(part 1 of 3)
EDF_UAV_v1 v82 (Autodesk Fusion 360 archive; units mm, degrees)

design "EDF_UAV_v1" references "UAV_test_rig", "fin_mount", "servo_savox_SH-0264MG"
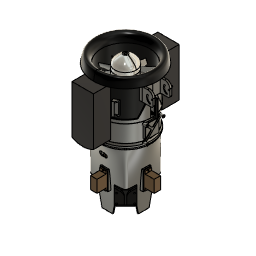
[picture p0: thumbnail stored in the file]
sketch "Sketch1" plane through (0, 0, 0) normal (0, 0, 1) x axis (1, 0, 0)
  circle C1 centre (0, 0) radius 44.7
  circle C2 centre (0, 0) radius 46.75
  point P1 (0, 0)
  point P2 (0, 0)
  coincident P1 P2
  concentric C1 C2
  dimension "d1" diameter C1 = 89.4
  dimension "d486" diameter C2 = 93.5
extrude "Extrude1" new body sketch "Sketch1" profile of C1 along normal blind 63
sketch "Sketch2" plane through (0, 0, 0) normal (0, 0, 1) x axis (1, 0, 0)
  circle C1 centre (0, 0) radius 21.6
  dimension "d51" diameter C1 = 43.2
extrude "Extrude2" new body sketch "Sketch2" along normal blind 40
sketch "Sketch8" plane through (0, 0, 0) normal (0, 0, -1) x axis (1, 0, 0)
  circle C1 centre (0, 0) radius 21.6
  circle C2 centre (0, 0) radius 21.6
  circle C3 centre (0, 0) radius 20
  point P1 (0, 0)
  point P3 (0, 0)
  coincident P1 P3
  concentric C2 C3
  equal C1 C2
  dimension "d176" diameter C3 = 40
extrude "Extrude7" cut sketch "Sketch8" profile of C3 against normal blind 30
sketch "Sketch9" plane through (0, 0, 40) normal (0, 0, 1) x axis (-1, 0, 0)
  line L1 (0, 27) -> (0, -28)
  line L2 (21.3145, -3.5) -> (12.25, -3.5)
  line L3 (21.3145, 3.5) -> (12.25, 3.5)
  line L4 (-14.3541, 0) -> (31.6459, 0)
  line L5 (-21.3145, 3.5) -> (-12.25, 3.5)
  line L6 (-21.3145, -3.5) -> (-12.25, -3.5)
  circle C1 centre (0, 0) radius 21.6
  circle C2 centre (0, 0) radius 21.6
  arc A1 centre (0, 0) radius 21.6 clockwise from (21.3145, 3.5) to (21.3145, -3.5)
  arc A2 centre (0, 0) radius 21.6 clockwise from (0, -21.6) to (0, 21.6)
  arc A3 centre (12.25, 0) radius 3.5 clockwise from (12.25, -3.5) to (12.25, 3.5)
  arc A4 centre (0, 0) radius 21.6 clockwise from (-21.3145, -3.5) to (-21.3145, 3.5)
  arc A5 centre (-12.25, 0) radius 3.5 clockwise from (-12.25, 3.5) to (-12.25, -3.5)
  point P5 (0, 0)
  point P7 (0, 0)
  point P12 (0, -21.6)
  point P13 (0, 21.6)
  point P14 (0, 0)
  point P6 (12.25, 0)
  point P17 (21.3145, 3.5)
  point P18 (21.3145, 3.5)
  point P9 (12.25, -3.5)
  point P25 (-12.25, -3.5)
  point P10 (21.3145, -3.5)
  point P20 (-21.3145, -3.5)
  point P11 (12.25, 3.5)
  point P22 (-12.25, 3.5)
  point P23 (-21.3145, 3.5)
  point P21 (-21.3145, 3.5)
  vertical L1
  coincident L1 P5
  coincident P5 P7
  equal C2 A1
  horizontal L2
  horizontal L3
  tangent L2 A3
  tangent L3 A3
  coincident L1 P12
  coincident L1 P13
  concentric A1 A2
  horizontal L4
  coincident P14 L4
  coincident P6 L4
  coincident A1 P17
  coincident L3 P18
  symmetric L1 P9 P25
  symmetric L1 P10 P20
  symmetric L1 P11 P22
  symmetric L1 A1 A4
  symmetric L1 A3 A5
  symmetric L1 P17 P23
  symmetric L1 P18 P21
  dimension "d177" distance L2 L3 = 7
  dimension "d178" = 24.5
extrude "Extrude8" cut sketch "Sketch9" profile of C1 A3 A2 C2 L2 L3 A4 L5 A5 L6 against normal blind 7
sketch "Sketch10" plane through (0, 0, 40) normal (0, 0, 1) x axis (-1, 0, 0)
  line L1 (-12.25, 3.5) -> (-21.3145, 3.5)
  line L2 (-21.3145, -3.5) -> (-12.25, -3.5)
  line L3 (12.25, -3.5) -> (21.3145, -3.5)
  line L4 (21.3145, 3.5) -> (12.25, 3.5)
  line L5 (-28.5897, 0) -> (22.8656, 0)
  line L6 (0, 21.6) -> (0, -27)
  line L7 (0, 0) -> (7.7782, -7.7782)
  line L8 (-7.7782, -7.7782) -> (0, 0)
  arc A1 centre (-12.25, 0) radius 3.5 clockwise from (-12.25, 3.5) to (-12.25, -3.5)
  arc A2 centre (0, 0) radius 21.6 clockwise from (21.3145, -3.5) to (-21.3145, -3.5)
  arc A3 centre (12.25, 0) radius 3.5 clockwise from (12.25, -3.5) to (12.25, 3.5)
  arc A4 centre (0, 0) radius 21.6 clockwise from (-21.3145, 3.5) to (21.3145, 3.5)
  arc A5 centre (0, 0) radius 11 clockwise from (7.7782, -7.7782) to (-7.7782, -7.7782)
  arc A6 centre (0, 0) radius 12.5 clockwise from (8.8388, -8.8388) to (-8.8388, -8.8388)
  arc A7 centre (0, 0) radius 9.5 clockwise from (6.7175, -6.7175) to (-6.7175, -6.7175)
  arc A8 centre (-7.7782, -7.7782) radius 1.5 clockwise from (-8.8388, -8.8388) to (-6.7175, -6.7175)
  arc A9 centre (7.7782, -7.7782) radius 1.5 clockwise from (6.7175, -6.7175) to (8.8388, -8.8388)
  circle C1 centre (0, 0) radius 7
  arc A10 centre (0, 0) radius 9.5 clockwise from (-6.7175, 6.7175) to (6.7175, 6.7175)
  arc A11 centre (7.7782, 7.7782) radius 1.5 clockwise from (8.8388, 8.8388) to (6.7175, 6.7175)
  arc A12 centre (0, 0) radius 12.5 clockwise from (-8.8388, 8.8388) to (8.8388, 8.8388)
  arc A13 centre (-7.7782, 7.7782) radius 1.5 clockwise from (-6.7175, 6.7175) to (-8.8388, 8.8388)
  circle C2 centre (12.25, 0) radius 1.5
  point P17 (0, 0)
  point P23 (0, 0)
  point P18 (8.8388, 8.8388)
  point P24 (8.8388, -8.8388)
  point P13 (-8.8388, -8.8388)
  point P15 (-8.8388, 8.8388)
  point P19 (-6.7175, 6.7175)
  point P25 (-6.7175, -6.7175)
  point P22 (6.7175, 6.7175)
  point P26 (6.7175, -6.7175)
  point P1 (0, 0)
  point P32 (0, 21.6)
  point P14 (-7.7782, -7.7782)
  point P30 (7.7782, -7.7782)
  point P33 (7.7782, -7.7782)
  point P34 (0, 0)
  point P35 (0, 0)
  point P36 (-7.7782, -7.7782)
  point P29 (12.25, 0)
  tangent A6 A8
  tangent A7 A8
  tangent A7 A9
  tangent A6 A9
  coincident P17 P23
  coincident P17 L5
  symmetric P18 P24 L5
  symmetric P13 P15 L5
  symmetric P19 P25 L5
  symmetric P22 P26 L5
  symmetric A6 L5 A12
  symmetric A8 L5 A13
  symmetric A7 L5 A10
  symmetric A9 L5 A11
  horizontal L5
  coincident P1 L5
  coincident P1 P17
  midpoint A4 P32
  vertical L6
  symmetric P14 P30 L6
  coincident P30 P33
  coincident P17 P34
  coincident P1 P35
  coincident P14 P36
  coincident P29 L5
  concentric A3 C2
  dimension "d179" diameter C1 = 14
  dimension "d180" diameter C2 = 3
  dimension "d181" distance A6 A7 = 3
  dimension "d182" diameter A5 = 22
  dimension "d183" angle L7 L8 = 90
extrude "Extrude9" cut sketch "Sketch10" profile of A6 A7 A8 A9 C1 A10 A11 A12 A13 no distance stored
work_plane "WorkPlane1" RotateAngle 0
sketch "Sketch3" plane through (0, -21.6, 25.8865) normal (0, -1, 0) x axis (1, 0, 0)
  curve K1 (1, 3) -> (3, -23.8865)
  curve K2 (3, -23.8865) -> (1, 3)
  line L1 (-44.7, -25.8865) -> (44.7, -25.8865)
  point P2 (3, -23.8865)
  point P4 (4, 6.1135)
  dimension "d10" distance P2 L1 = 2
  dimension "d11" distance P2 P4 = 30
extrude "Extrude3" add sketch "Sketch3" profile of K1 K2 to an object Side2Offset 0
circular_pattern "C-Pattern1" TotalAngle 360
work_plane "WorkPlane2" RotateAngle 0
sketch "Sketch5" plane through (-44.7, 0, 31.321) normal (1, 0, 0) x axis (0, 1, 0)
  line L1 (3.2, -1.321) -> (0, -1.321)
  line L2 (3.2, -31.321) -> (3.2, -1.321)
  line L3 (0, -31.321) -> (3.2, -31.321)
  line L4 (0, -1.321) -> (0, -31.321)
  point P6 (0, -31.321)
  point P4 (3.2, -31.321)
  point P5 (0, -31.321)
  point P3 (3.2, -1.321)
  horizontal L1
  vertical L2
  horizontal L3
  vertical L4
  coincident L3 P6
  coincident L4 P6
  dimension "d27" distance P4 P5 = 3.2
  dimension "d28" distance P3 P4 = 30
extrude "Extrude5" add sketch "Sketch5" blind -12 Side2Offset 0
sketch "Sketch6" plane through (0, 0, 0) normal (0, -1, 0) x axis (1, 0, 0)
  line L1 (-46.75, 0) -> (-56.7, 0)
  line L2 (-56.7, 0) -> (-56.7, 30)
  line L3 (-56.7, 30) -> (-46.75, 30)
  line L4 (-46.75, 30) -> (-46.75, 0)
  circle C1 centre (-51.2, 22.5) radius 1.65
  circle C2 centre (-51.2, 7.5) radius 1.65
  point P6 (-51.2, 22.5)
  point P7 (-51.2, 7.5)
  vertical P6 P7
  equal C1 C2
  dimension "d39" diameter C1 = 3.3
  dimension "d40" distance L2 P6 = 5.5
  dimension "d42" distance P6 P7 = 15
  dimension "d46" distance L1 P7 = 7.5
extrude "Extrude6" cut sketch "Sketch6" profile of C1 C2 no distance stored
mirror "Mirror2" mirrorStitchTolerance 0.1
sketch "Sketch7" plane through (0, 0, 40) normal (0, 0, 1) x axis (-1, 0, 0)
  line L1 (-12.25, 3.5) -> (-21.3145, 3.5)
  line L2 (-21.3145, -3.5) -> (-12.25, -3.5)
  line L3 (12.25, -3.5) -> (21.3145, -3.5)
  line L4 (21.3145, 3.5) -> (12.25, 3.5)
  circle C1 centre (0, 0) radius 20
  circle C2 centre (0, 0) radius 21.6
  arc A1 centre (-12.25, 0) radius 3.5 clockwise from (-12.25, 3.5) to (-12.25, -3.5)
  arc A2 centre (12.25, 0) radius 3.5 clockwise from (12.25, -3.5) to (12.25, 3.5)
  arc A3 centre (0, 0) radius 21.6 clockwise from (-21.3145, 3.5) to (21.3145, 3.5)
  arc A4 centre (0, 0) radius 21.6 clockwise from (21.3145, -3.5) to (-21.3145, -3.5)
  arc A5 centre (0, 0) radius 9.5 clockwise from (6.7175, -6.7175) to (-6.7175, -6.7175)
  arc A6 centre (7.7782, -7.7782) radius 1.5 clockwise from (6.7175, -6.7175) to (8.8388, -8.8388)
  arc A7 centre (0, 0) radius 12.5 clockwise from (8.8388, -8.8388) to (-8.8388, -8.8388)
  arc A8 centre (-7.7782, -7.7782) radius 1.5 clockwise from (-8.8388, -8.8388) to (-6.7175, -6.7175)
  circle C3 centre (0, 0) radius 7
  arc A9 centre (0, 0) radius 9.5 clockwise from (-6.7175, 6.7175) to (6.7175, 6.7175)
  arc A10 centre (-7.7782, 7.7782) radius 1.5 clockwise from (-6.7175, 6.7175) to (-8.8388, 8.8388)
  arc A11 centre (0, 0) radius 12.5 clockwise from (-8.8388, 8.8388) to (8.8388, 8.8388)
  arc A12 centre (7.7782, 7.7782) radius 1.5 clockwise from (8.8388, 8.8388) to (6.7175, 6.7175)
  arc A13 centre (0, 0) radius 21.6 clockwise from (-21.3145, 3.5) to (21.3145, 3.5)
  concentric C1 C2
  dimension "d134" diameter C1 = 40
extrude "Extrude10" cut sketch "Sketch7" profile of C1 C2 against normal blind 7
chamfer "Chamfer2" distance 7
sketch "Sketch1" plane through (0, 0, 0) normal (0, 0, 1) x axis (1, 0, 0)
  circle C1 centre (0, 0) radius 20
  circle C2 centre (0, 0) radius 21.6
  circle C3 centre (0, 0) radius 21.6
  point P1 (0, 0)
  point P2 (0, 0)
  coincident P1 P2
  concentric C1 C2
  equal C2 C3
  dimension "d124" diameter C1 = 40
extrude "Extrude1" new body sketch "Sketch1" profile of C1 along normal blind 23.5
sketch "Sketch2" plane through (0, 0, 23.5) normal (0, 0, 1) x axis (-1, 0, 0)
  circle C1 centre (0, 0) radius 20
  circle C2 centre (0, 0) radius 18.25
  circle C3 centre (0, 0) radius 20
  point P1 (0, 0)
  point P3 (0, 0)
  coincident P1 P3
  concentric C2 C3
  equal C1 C3
  dimension "d75" diameter C2 = 36.5
extrude "Extrude2" cut sketch "Sketch2" against normal blind 3
sketch "Sketch3" plane through (0, 0, 23.5) normal (0, 0, 1) x axis (-1, 0, 0)
  circle C1 centre (0, 0) radius 18.25
  circle C2 centre (0, 0) radius 4
  point P1 (0, 0)
  point P3 (0, 0)
  coincident P1 P3
  dimension "d78" diameter C2 = 8
extrude "Extrude3" cut sketch "Sketch3" profile of C2 no distance stored
sketch "Sketch4" plane through (0, 0, 0) normal (0, 0, -1) x axis (1, 0, 0)
  circle C1 centre (0, 0) radius 4
  circle C2 centre (0, 0) radius 20
  circle C3 centre (0, 0) radius 6
  point P1 (0, 0)
  point P3 (0, 0)
  coincident P1 P3
  dimension "d80" diameter C3 = 12
extrude "Extrude4" cut sketch "Sketch4" profile of C1 C3 against normal blind 8
sketch "Sketch5" plane through (0, 0, 0) normal (0, 0, -1) x axis (1, 0, 0)
  circle C1 centre (0, 0) radius 6
  circle C2 centre (0, 0) radius 20
  circle C3 centre (0, 0) radius 6
  circle C4 centre (0, 0) radius 12.5
  concentric C1 C3
  equal C1 C3
  concentric C3 C4
  dimension "d84" diameter C4 = 25
extrude "Extrude5" cut sketch "Sketch5" profile of C1 C3 C4 against normal blind 12
chamfer "Chamfer1" distance 7 distance 12
ground "Ground1"
work_plane "WorkPlane1" RotateAngle 0
sketch "Sketch7" plane through (-3.2407, -19.7357, 12.3408) normal (-0.162, -0.9868, 0) x axis (-0.9868, 0.162, 0)
  curve K1 (0, -7) -> (0, -7)
work_plane "WorkPlane2" AlongDistance 22
sketch "Sketch8" plane through (-6.8056, -41.445, 12.3408) normal (-0.162, -0.9868, 0) x axis (-0.9868, 0.162, 0)
  curve K1 (1, -2) -> (1, -2)
loft "Loft1" sketch "Sketch7" + "Sketch8"
extrude "Extrude6" add of existing geometry to an object
circular_pattern "C-Pattern1" countU 11 TotalAngle 360
joint "Assemble2" alignAngle 0 alignOffsetX 0 alignOffsetY 0 alignOffsetZ 0
sketch "Sketch1" plane through (0, 0, 0) normal (0, 1, 0) x axis (1, 0, 0)
  line L1 (19.85, -40) -> (19.85, -33)
  curve K1 (4.5, -57) -> (19.85, -40)
  line L2 (0, -57) -> (4.5, -57)
  line L3 (0, -34) -> (0, -90)
  line L4 (0, -55.4) -> (0, -57)
  line L5 (19.85, -33) -> (18.25, -33)
  curve K2 (2.0435, -58.4183) -> (6.9565, -55.5817)
  line L6 (22.5, -33) -> (1.75, -33)
  line L7 (18.25, -40) -> (18.25, -33)
  curve K3 (4.0675, -55.4) -> (18.25, -40)
  line L8 (0, -55.4) -> (4.0675, -55.4)
  point P11 (0, -33)
  point P5 (4.5, -57)
  point P2 (19.85, -33)
  point P3 (19.85, -40)
  vertical L1
  horizontal L2
  vertical L3
  perpendicular L1 L5
  coincident L3 P11
  midpoint P5 K2
  collinear L5 L6
  collinear L3 L4
  dimension "d108" = 9
  dimension "d109" = 1.6
  dimension "d110" distance L2 L5 = 24
  dimension "d112" = 36.5
  dimension "d113" angle L2 K2 = 150
  dimension "d114" distance P2 P3 = 7
revolve "Revolve1" sketch "Sketch1" AlongAngle 360
sketch "Sketch2" plane through (0, 0, 57) normal (0, 0, 1) x axis (-1, 0, 0)
  circle C1 centre (0, 0) radius 4.5
  circle C2 centre (0, 0) radius 1.5
  point P1 (0, 0)
  point P3 (0, 0)
  coincident P1 P3
  dimension "d116" diameter C2 = 3
extrude "Extrude1" cut sketch "Sketch2" profile of C2 no distance stored
chamfer "Chamfer1" distance 1 distance 1
joint "Assemble3" alignAngle 0 alignOffsetX 0 alignOffsetY 0 alignOffsetZ 0
sketch "Sketch1" plane through (0, 0, 30) normal (0, 0, -1) x axis (1, 0, 0)
  circle C1 centre (0, 0) radius 19.5
  arc A1 centre (0, 0) radius 9.5 clockwise from (6.7175, -6.7175) to (-6.7175, -6.7175)
  arc A2 centre (7.7782, -7.7782) radius 1.5 clockwise from (6.7175, -6.7175) to (8.8388, -8.8388)
  arc A3 centre (0, 0) radius 12.5 clockwise from (8.8388, -8.8388) to (-8.8388, -8.8388)
  arc A4 centre (-7.7782, -7.7782) radius 1.5 clockwise from (-8.8388, -8.8388) to (-6.7175, -6.7175)
  circle C2 centre (0, 0) radius 7
  arc A5 centre (0, 0) radius 9.5 clockwise from (-6.7175, 6.7175) to (6.7175, 6.7175)
  arc A6 centre (-7.7782, 7.7782) radius 1.5 clockwise from (-6.7175, 6.7175) to (-8.8388, 8.8388)
  arc A7 centre (0, 0) radius 12.5 clockwise from (-8.8388, 8.8388) to (8.8388, 8.8388)
  arc A8 centre (7.7782, 7.7782) radius 1.5 clockwise from (8.8388, 8.8388) to (6.7175, 6.7175)
  circle C3 centre (0, 0) radius 20
  point P1 (0, 0)
  point P2 (0, 0)
  coincident P1 P2
  dimension "d125" diameter C1 = 39
extrude "Extrude1" new body sketch "Sketch1" profile of C1 along normal blind 70
chamfer "Chamfer1" distance 4 distance 4
position "Position1"
joint "Assemble4" alignAngle 0 alignOffsetX 0 alignOffsetY 0 alignOffsetZ 0
sketch "Sketch1" plane through (0, 0, 0) normal (0, 1, 0) x axis (1, 0, 0)
  line L1 (0, -53.7902) -> (0, 85.3819)
  line L2 (45, 0) -> (45, 40)
  line L3 (46.8, 0) -> (45, 0)
  line L4 (46.8, -30) -> (46.8, 0)
  line L5 (39.5, 165) -> (37.5, 165)
  line L6 (48.8, -30) -> (48.8, 2)
  line L7 (48.8, 2) -> (47, 2)
  line L8 (47, 2) -> (47, 40)
  line L9 (48.8, -30) -> (46.8, -30)
  line L10 (47, 40) -> (45, 40)
  line L11 (46.6404, 0) -> (-46.6404, 0)
  line L12 (46.75, -30) -> (46.75, 0)
  line L13 (46.75, -63) -> (-46.75, -63)
  point P1 (0, 0)
  point P4 (45, 40)
  point P6 (45, 0)
  point P7 (46.8, 0)
  point P8 (46.8, -30)
  vertical L1
  coincident P1 L1
  vertical L2
  perpendicular L2 L3
  perpendicular L3 L4
  coincident P1 L3
  parallel L4 L6
  parallel L3 L7
  parallel L2 L8
  perpendicular L8 L10
  horizontal L9
  dimension "d165" = 90
  dimension "d168" distance P4 P6 = 40
  dimension "d172" distance P7 P8 = 30
  dimension "d254" distance L2 L8 = 2
  dimension "d255" distance L4 L6 = 2
  dimension "d263" distance L3 L7 = 2
  dimension "d487" distance L4 L12 = 0.05
position "Position2"
revolve "Revolve3" sketch "Sketch1" AlongAngle 360
joint "Assemble5" alignAngle 0 alignOffsetX 0 alignOffsetY 0 alignOffsetZ 0
work_plane "WorkPlane6" AlongDistance 120
sketch "Sketch11" plane through (0, 0, -160) normal (0, 0, -1) x axis (1, 0, 0)
  line L1 (-29.5, 32) -> (29.5, 32)
  line L2 (-32, -29.5) -> (-32, 29.5)
  line L3 (29.5, -32) -> (-29.5, -32)
  line L4 (32, 29.5) -> (32, -29.5)
  line L5 (0, -22.5) -> (0, -1.75)
  line L6 (2.9497, 0) -> (16.9903, 0)
  line L7 (34, 29.5) -> (34, -29.5)
  line L8 (-29.5, 34) -> (29.5, 34)
  line L9 (-34, -29.5) -> (-34, 29.5)
  line L10 (29.5, -34) -> (-29.5, -34)
  arc A1 centre (29.5, -29.5) radius 2.5 clockwise from (32, -29.5) to (29.5, -32)
  arc A2 centre (-29.5, -29.5) radius 2.5 clockwise from (-29.5, -32) to (-32, -29.5)
  arc A3 centre (-29.5, 29.5) radius 2.5 clockwise from (-32, 29.5) to (-29.5, 32)
  arc A4 centre (29.5, 29.5) radius 2.5 clockwise from (29.5, 32) to (32, 29.5)
  arc A5 centre (29.5, 29.5) radius 4.5 clockwise from (29.5, 34) to (34, 29.5)
  arc A6 centre (-29.5, 29.5) radius 4.5 clockwise from (-34, 29.5) to (-29.5, 34)
  arc A7 centre (-29.5, -29.5) radius 4.5 clockwise from (-29.5, -34) to (-34, -29.5)
  arc A8 centre (29.5, -29.5) radius 4.5 clockwise from (34, -29.5) to (29.5, -34)
  point P1 (0, 0)
  point P2 (0, 0)
  point P3 (0, 0)
  horizontal L1
  perpendicular L1 L2
  parallel L1 L3
  parallel L2 L4
  coincident P1 P2
  coincident P1 P3
  tangent L3 A1
  tangent L4 A1
  symmetric L2 L4 L5
  symmetric L1 L3 L6
  tangent L3 A2
  tangent L2 A2
  tangent L2 A3
  tangent L1 A3
  tangent L1 A4
  tangent L4 A4
  equal L1 L2
  dimension "d277" diameter A1 = 5
  dimension "d278" distance L1 L3 = 64
  dimension "d280" diameter A2 = 5
  dimension "d281" diameter A3 = 5
  dimension "d282" diameter A4 = 5
  dimension "d283" = 2
work_plane "WorkPlane7" AlongDistance 0
sketch "Sketch12" plane through (0, 0, -40) normal (0, 0, -1) x axis (1, 0, 0)
  circle C1 centre (0, 0) radius 45
  circle C2 centre (0, 0) radius 47
  point P1 (0, 0)
  point P2 (0, 0)
  coincident P1 P2
  concentric C1 C2
  dimension "d265" diameter C1 = 90
  dimension "d270" diameter C2 = 94
loft "Loft3" sketch "Sketch12" + "Sketch11" End TakeOff Angle 0
loft "Loft4" sketch "Sketch12" + "Sketch11" End TakeOff Angle 0
work_plane "WorkPlane8" RotateAngle 0
work_plane "WorkPlane11" AlongDistance -35
sketch "Sketch13" plane through (0, -35, 0) normal (0, 1, 0) x axis (1, 0, 0)
  line L1 (-40, 160) -> (-10, 160)
  line L2 (-40, 115) -> (-40, 160)
  line L3 (-19, 115) -> (-40, 115)
  line L4 (-10, 160) -> (-19, 115)
  line L5 (-29.5, 160) -> (29.5, 160)
  line L6 (0, 124) -> (0, 160)
  point P8 (0, 160)
  point P3 (-40, 160)
  point P4 (-40, 115)
  point P2 (-10, 160)
  point P10 (0, 160)
  point P5 (-19, 115)
  point P9 (0, 124)
  horizontal L1
  vertical L2
  horizontal L3
  collinear L1 L5
  midpoint L5 P8
  perpendicular L5 L6
  dimension "d291" distance P3 P4 = 45
  dimension "d292" distance P2 P10 = 10
  dimension "d293" distance P5 P9 = 19
extrude "Extrude8" cut sketch "Sketch13" profile of L1 L2 L3 L4 L5 along normal blind 4
circular_pattern "C-Pattern5" TotalAngle 360
mirror "Mirror1" mirrorStitchTolerance 0.1
circular_pattern "C-Pattern6" TotalAngle 360
fillet "Fillet1" radius 5
work_plane "WorkPlane12" RotateAngle 0
sketch "Sketch14" plane through (47, 0, -21) normal (1, 0, 0) x axis (0, 1, 0)
  line L1 (0, -121.925) -> (0, 0)
  line L2 (-6, -72.5) -> (6, -72.5)
  line L3 (-6, -95.3) -> (-6, -72.5)
  line L4 (6, -95.3) -> (-6, -95.3)
  line L5 (6, -72.5) -> (6, -95.3)
  line L6 (-6, -95.3) -> (6, -72.5)
  line L7 (6, -95.3) -> (-6, -72.5)
  line L8 (-47.5057, -139) -> (47.5057, -139)
  circle C1 centre (0, -69.7) radius 0.5
  circle C2 centre (0, -98.1) radius 0.5
  point P1 (0, 0)
  point P2 (0, 0)
  point P4 (0, -69.7)
  point P5 (0, -98.1)
  point P10 (0, -83.9)
  point P7 (-6, -72.5)
  point P8 (-6, -95.3)
  point P6 (6, -72.5)
  coincident P1 P2
  vertical L1
  coincident L1 P4
  coincident L1 P5
  equal C1 C2
  horizontal L2
  perpendicular L2 L3
  parallel L2 L4
  parallel L3 L5
  coincident L6 P10
  coincident L7 P10
  coincident L1 P10
  dimension "d305" diameter C1 = 1
  dimension "d306" distance P4 P5 = 28.4
  dimension "d307" distance P7 P8 = 22.8
  dimension "d308" distance P6 P7 = 12
  dimension "d328" distance P5 L4 = 2.8
  dimension "d420" distance L4 L8 = 43.7
extrude "Extrude9" cut sketch "Sketch14" profile of C1 C2 L2 L3 L4 L5 no distance stored
circular_pattern "C-Pattern7" TotalAngle 90
component_insert "Component Insert3"
joint "Assemble2" alignAngle 0 alignOffsetX 0 alignOffsetY 0 alignOffsetZ -5
component_insert "Component Insert4"
joint "Assemble3" alignAngle 0 alignOffsetX 0 alignOffsetY 0 alignOffsetZ 0
component_insert "Component Insert5"
joint "Assemble4" alignAngle 0 alignOffsetX 0 alignOffsetY 0 alignOffsetZ 5
component_insert "Component Insert6"
joint "Assemble5" alignAngle 0 alignOffsetX 0 alignOffsetY 0 alignOffsetZ 0
component_insert "Component Insert7"
joint "Assemble6" alignAngle 90 alignOffsetX 0 alignOffsetY 0 alignOffsetZ 5
component_insert "Component Insert8"
joint "Assemble7" alignAngle 0 alignOffsetX 0 alignOffsetY 0 alignOffsetZ 0
component_insert "Component Insert9"
joint "Assemble8" alignAngle 90 alignOffsetX 0 alignOffsetY 0 alignOffsetZ -5
component_insert "Component Insert10"
joint "Assemble9" alignAngle 0 alignOffsetX 0 alignOffsetY 0 alignOffsetZ 0
position "Position3"
sketch "Sketch1" plane through (0, -40.0805, 0) normal (0, 1, 0) x axis (-1, 0, 0)
  line L1 (-6, -93.5) -> (-6, -88.7)
  line L2 (6, -93.5) -> (-6, -93.5)
  line L3 (6, -88.7) -> (6, -93.5)
  line L4 (-7.5, -87.2) -> (7.5, -87.2)
  line L5 (-7.5, -122.6) -> (-7.5, -87.2)
  line L6 (7.5, -122.6) -> (-7.5, -122.6)
  line L7 (7.5, -87.2) -> (7.5, -122.6)
  line L8 (-6, -93.5) -> (6, -93.5)
  line L9 (-6, -116.3) -> (-6, -93.5)
  line L10 (6, -116.3) -> (-6, -116.3)
  line L11 (6, -93.5) -> (6, -116.3)
  line L12 (0, -119.1) -> (0, -90.7)
  circle C1 centre (0, -90.7) radius 1.25
  circle C2 centre (0, -90.7) radius 0.6
  circle C3 centre (0, -119.1) radius 0.6
  circle C4 centre (0, -119.1) radius 1.25
  point P5 (-6, -93.5)
  point P17 (-6, -116.3)
  point P18 (6, -116.3)
  point P2 (0, -90.7)
  point P20 (0, -90.7)
  point P12 (0, -119.1)
  point P21 (0, -119.1)
  point P3 (6, -88.7)
  point P22 (6, -121.1)
  horizontal L4
  vertical L5
  horizontal L6
  vertical L7
  concentric C1 C2
  horizontal L8
  vertical L9
  horizontal L10
  vertical L11
  coincident P5 L8
  coincident L10 P17
  coincident L11 P18
  coincident L9 P17
  coincident P2 P20
  coincident P12 P21
  perpendicular L10 L12
  concentric C3 C4
  equal C2 C3
  dimension "d349" distance L3 L7 = 1.5
  dimension "d352" distance P3 L4 = 1.5
  dimension "d353" distance L6 P22 = 1.5
  dimension "d421" diameter C2 = 1.2
extrude "Extrude1" new body sketch "Sketch1" profile of L1 L2 L3 L4 L5 L6 L7 C2 C3 L8 L9 L10 L11 to an object
step "C-Pattern" TotalAngle 360
work_plane "WorkPlane13" AlongDistance 48.5
sketch "Sketch15" plane through (48.5, 0, 0) normal (1, 0, 0) x axis (0, 1, 0)
  line L1 (3.2, 0) -> (3.2, 30)
  line L2 (3.2, 30) -> (0, 30)
  line L3 (0, 30) -> (0, 0)
  line L4 (0, 0) -> (3.2, 0)
  line L5 (3.25, -0.05) -> (3.25, 30)
  line L6 (-0.05, -0.05) -> (3.25, -0.05)
  line L7 (-0.05, 30) -> (-0.05, -0.05)
  line L8 (-0.05, 30) -> (3.25, 30)
  perpendicular L7 L8
  dimension "d477" = -0.05
work_plane "WorkPlane20" AlongDistance 7
sketch "Sketch16" plane through (55.5, 0, 0) normal (1, 0, 0) x axis (0, 1, 0)
  line L1 (3.2, 0) -> (0, 0)
  line L2 (3.2, 30) -> (3.2, 0)
  line L3 (0, 30) -> (3.2, 30)
  line L4 (0, 0) -> (0, 30)
  line L5 (5.2, 30) -> (5.2, -1.6)
  line L6 (-2, 30) -> (5.2, 30)
  line L7 (-2, -1.6) -> (-2, 30)
  line L8 (5.2, -1.6) -> (-2, -1.6)
  point P5 (0, 30)
  vertical L5
  horizontal L6
  vertical L7
  coincident P5 L6
  perpendicular L5 L8
  dimension "d361" distance L2 L5 = 2
  dimension "d363" distance L4 L7 = 2
  dimension "d490" distance L1 L8 = 1.6
extrude "Extrude11" add sketch "Sketch16" profile of L2 L3 L4 L5 L6 L7 L8 to an object
chamfer "Chamfer20" distance 6.9
sketch "Sketch17" plane through (0, -2, 0) normal (0, -1, 0) x axis (1, 0, 0)
  line L1 (48.759, -1.441) -> (48.759, 30)
  line L2 (55.5, 30) -> (55.5, 5.3)
  line L3 (48.759, 30) -> (55.5, 30)
  line L4 (55.5, 5.3) -> (48.759, -1.441)
  circle C1 centre (51.2, 22.5) radius 1.65
  circle C2 centre (51.2, 7.5) radius 1.65
  circle C3 centre (51.2, 22.5) radius 1.67
  circle C4 centre (51.2, 7.5) radius 1.67
  concentric C1 C3
  concentric C2 C4
  equal C3 C4
  dimension "d512" distance C1 C3 = 0.02
extrude "Extrude12" cut sketch "Sketch17" profile of C3 C4 no distance stored
sketch "Sketch18" plane through (0, -2, 0) normal (0, -1, 0) x axis (1, 0, 0)
  line L1 (48.759, -1.441) -> (48.759, 30)
  line L2 (55.5, 30) -> (55.5, 5.3)
  line L3 (48.759, 30) -> (55.5, 30)
  line L4 (53.95, 24.0877) -> (53.95, 20.9123)
  line L5 (51.2, 25.6754) -> (53.95, 24.0877)
  line L6 (48.45, 24.0877) -> (51.2, 25.6754)
  line L7 (48.45, 20.9123) -> (48.45, 24.0877)
  line L8 (51.2, 19.3246) -> (48.45, 20.9123)
  line L9 (53.95, 20.9123) -> (51.2, 19.3246)
  line L10 (48.45, 9.0877) -> (51.2, 10.6754)
  line L11 (48.45, 5.9123) -> (48.45, 9.0877)
  line L12 (51.2, 4.3246) -> (48.45, 5.9123)
  line L13 (53.95, 5.9123) -> (51.2, 4.3246)
  line L14 (53.95, 9.0877) -> (53.95, 5.9123)
  line L15 (51.2, 10.6754) -> (53.95, 9.0877)
  line L16 (55.5, 5.3) -> (48.759, -1.441)
  circle C1 centre (51.2, 22.5) radius 1.67
  circle C2 centre (51.2, 7.5) radius 1.67
  point P12 (51.2, 22.5)
  point P19 (51.2, 7.5)
  vertical L7
  vertical L11
  dimension "d370" distance P12 L9 = 2.75 (= "( 5.5 / 2 ) * 1 mm")
  dimension "d371" distance P19 L15 = 2.75 (= "( 5.5 / 2 ) * 1 mm")
extrude "Extrude13" cut sketch "Sketch18" profile of L1 L4 L5 L6 L8 L9 L10 L12 L13 L14 L15 against normal blind 0.6
mirror "Mirror2" mirrorStitchTolerance 0.1
extrude "Extrude11" cut sketch "Sketch15" no distance stored
chamfer "Chamfer13" distance 1.5
work_plane "WorkPlane22" RotateAngle 0
sketch "Sketch30" plane through (0, -48.8, 12.3663) normal (0, -1, 0) x axis (1, 0, 0)
  line L1 (-48.759, 17.6337) -> (48.759, 17.6337)
  line L2 (-54.9889, -8.3663) -> (-70, 17.6337)
  line L3 (54.9889, -8.3663) -> (-54.9889, -8.3663)
  line L4 (70, 17.6337) -> (54.9889, -8.3663)
  line L5 (0, 10.1337) -> (0, -10.6163)
  line L6 (-48.8, -14.3663) -> (48.8, -14.3663)
  line L7 (70, 17.6337) -> (-70, 17.6337)
  point P4 (-70, 17.6337)
  point P7 (70, 17.6337)
  coincident L1 P4
  parallel L1 L3
  coincident L1 P7
  symmetric L2 L4 L5
  dimension "d495" distance L3 L6 = 6
  dimension "d496" distance P4 P7 = 140
  dimension "d497" angle L3 L4 = 60
emboss "Emboss1" sketch "Sketch30" Depth -2 Horizontal Distance 0 Vertical Distance 0 Rotation Angle 0
work_plane "WorkPlane23" RotateAngle 0
sketch "Sketch31" plane through (0, 48.8, 12.2186) normal (0, 1, 0) x axis (1, 0, 0)
  line L1 (48.5222, -17.7814) -> (-48.5222, -17.7814)
  line L2 (48.8, 14.2186) -> (-48.8, 14.2186)
  line L3 (-66, -17.7814) -> (66, -17.7814)
  line L4 (-50.9889, 8.2186) -> (-66, -17.7814)
  line L5 (50.9889, 8.2186) -> (-50.9889, 8.2186)
  line L6 (66, -17.7814) -> (50.9889, 8.2186)
  line L7 (0, -10.2814) -> (0, 10.4686)
  point P6 (66, -17.7814)
  point P7 (-66, -17.7814)
  coincident L1 P6
  coincident L1 P7
  horizontal L5
  symmetric L4 L6 L7
  dimension "d505" distance L2 L5 = 6
  dimension "d506" angle L4 L5 = 60
  dimension "d507" distance P6 P7 = 132
emboss "Emboss2" sketch "Sketch31" Depth -2 Horizontal Distance 0 Vertical Distance 0 Rotation Angle 0
work_plane "WorkPlane14" AlongDistance -60
sketch "Sketch19" plane through (0, -60, 0) normal (0, 1, 0) x axis (1, 0, 0)
  line L1 (3.5, 61) -> (-3.5, 61)
  line L2 (-3.5, 69) -> (3.5, 69)
  line L3 (3.5, 65) -> (-3.5, 65)
  line L4 (-10, 160) -> (10, 160)
  line L5 (0, -22.5) -> (0, -1.75)
  arc A1 centre (3.5, 65) radius 4 clockwise from (3.5, 69) to (3.5, 61)
  arc A2 centre (-3.5, 65) radius 4 clockwise from (-3.5, 61) to (-3.5, 69)
  point P8 (0, 65)
  point P6 (-3.5, 65)
  point P7 (3.5, 65)
  tangent L1 A1
  tangent A1 L2
  parallel L1 L2
  tangent L2 A2
  tangent L1 A2
  horizontal L3
  midpoint L3 P8
  coincident P8 L5
  dimension "d377" distance P8 L4 = 95
  dimension "d378" distance P6 P7 = 7
  dimension "d379" distance L1 L2 = 8
extrude "Extrude14" cut sketch "Sketch19" profile of L1 A1 L2 A2 to an object
work_plane "WorkPlane15" AlongDistance -36
sketch "Sketch20" plane through (0, -36, 0) normal (0, 1, 0) x axis (1, 0, 0)
  line L1 (-10, 160) -> (-18.1961, 119.0194)
  curve K1 (-23.099, 115) -> (-18.1961, 119.0194)
  line L2 (18.1961, 119.0194) -> (10, 160)
  curve K2 (18.1961, 119.0194) -> (23.099, 115)
  line L3 (-10, 160) -> (10, 160)
  line L4 (-23.099, 115) -> (-31, 115)
  line L5 (31, 115) -> (23.099, 115)
  line L6 (-23.099, 111) -> (-31, 111)
  curve K3 (-23.099, 111) -> (-14.2738, 118.235)
  line L7 (-6.7208, 156) -> (-14.2738, 118.235)
  line L8 (-6.7208, 156) -> (6.7208, 156)
  line L9 (14.2738, 118.235) -> (6.7208, 156)
  curve K4 (14.2738, 118.235) -> (23.099, 111)
  line L10 (31, 111) -> (23.099, 111)
  line L11 (-31, 115) -> (-31, 111)
  line L12 (31, 115) -> (31, 111)
  point P8 (-31, 115)
  point P18 (-31, 115)
  point P9 (31, 115)
  point P19 (31, 115)
  coincident P8 P18
  perpendicular L6 L11
  coincident P9 P19
  perpendicular L5 L12
  dimension "d383" = 4
work_plane "WorkPlane16" AlongDistance -40
work_plane "WorkPlane18" RotateAngle 25
sketch "Sketch25" plane through (-20.6238, 44.2278, 14.7102) normal (-0.4226, 0.9063, 0) x axis (0.9063, 0.4226, 0)
  line L1 (-9.2753, -20.4654) -> (0.7247, -20.4654)
  line L2 (-9.2753, 4.5346) -> (-9.2753, -20.4654)
  line L3 (0.7247, 4.5346) -> (-9.2753, 4.5346)
  line L4 (0.7247, -20.4654) -> (0.7247, 4.5346)
  line L5 (-4.2753, -15.2898) -> (-4.2753, -25.2898)
  point P2 (0.7247, -20.4654)
  point P5 (0.7247, 4.5346)
  point P3 (-9.2753, -20.4654)
  horizontal L1
  vertical L2
  horizontal L3
  vertical L4
  dimension "d429" distance P2 P5 = 25
  dimension "d430" distance P2 P3 = 10
extrude "Extrude16" new body sketch "Sketch25" profile of L1 L2 L3 L4 blind 4 Side2Offset 0 bodies "battery_strap_loop"
sketch "Sketch27" plane through (0.6568, 0.3063, 0) normal (0.9063, 0.4226, 0) x axis (-0.4226, 0.9063, 0)
  line L1 (52.8, 10.1756) -> (46.7444, 10.1756)
  line L2 (52.8, 35.1756) -> (52.8, 10.1756)
  line L3 (46.7444, 35.1756) -> (52.8, 35.1756)
  line L4 (50.8, 33.1756) -> (48.7946, 33.1756)
  line L5 (50.8, 12.1756) -> (50.8, 33.1756)
  line L6 (48.7946, 12.1756) -> (50.8, 12.1756)
  line L7 (48.7946, 33.1756) -> (48.7946, 12.1756)
  line L8 (46.7444, 10.1756) -> (46.7444, 35.1756)
  horizontal L4
  vertical L5
  horizontal L6
  vertical L7
  dimension "d448" distance L3 L4 = 2
  dimension "d449" distance L1 L6 = 2
  dimension "d450" distance L2 L5 = 2
extrude "Extrude18" cut sketch "Sketch27" profile of L4 L5 L6 L7 along a picked direction blind -12
chamfer "Chamfer25" distance 6 distance 5
fillet "Fillet9" radius 1.5
mirror "Mirror4" mirrorStitchTolerance 0.1 bodies "battery_strap_loop2"
mirror "Mirror5" mirrorStitchTolerance 0.1 bodies "battery_strap_loop3"
mirror "Mirror6" mirrorStitchTolerance 0.1 bodies "battery_strap_loop4"
work_plane "WorkPlane19" RotateAngle 0
sketch "Sketch28" plane through (47, 0, -17.6586) normal (1, 0, 0) x axis (0, 1, 0)
  line L1 (0, -17.3414) -> (0, 14.1586)
  line L2 (-12.5, 10.9086) -> (12.5, 10.9086)
  line L3 (-12.5, -14.0914) -> (-12.5, 10.9086)
  line L4 (12.5, -14.0914) -> (-12.5, -14.0914)
  line L5 (12.5, 10.9086) -> (12.5, -14.0914)
  line L6 (-12.5, -14.0914) -> (12.5, 10.9086)
  line L7 (12.5, -14.0914) -> (-12.5, 10.9086)
  line L8 (-47, 14.1586) -> (47, 14.1586)
  point P8 (0, -1.5914)
  point P1 (0, 0)
  point P5 (-12.5, 10.9086)
  point P6 (-12.5, -14.0914)
  horizontal L2
  perpendicular L2 L3
  parallel L2 L4
  parallel L3 L5
  coincident L6 P8
  coincident L7 P8
  coincident L1 P8
  equal L2 L5
  midpoint L1 P8
  vertical L1
  coincident P1 L1
  dimension "d528" distance P5 P6 = 25
  dimension "d885" distance L2 L8 = 3.25
extrude "Extrude19" new body sketch "Sketch28" profile of L2 L3 L4 L5 to an object second side blind -2 bodies "pcb_holder_adapter"
sketch "Sketch1" plane through (0, -2, 0) normal (0, -1, 0) x axis (1, 0, 0)
  line L1 (48.759, 5.7339) -> (51.2, 4.3246)
  line L2 (48.759, -1.441) -> (48.759, 5.7339)
  line L3 (55.5, 30) -> (55.5, 5.3)
  line L4 (48.759, 30) -> (55.5, 30)
  line L5 (48.759, 24.2661) -> (48.759, 30)
  line L6 (51.2, 25.6754) -> (48.759, 24.2661)
  line L7 (53.95, 24.0877) -> (51.2, 25.6754)
  line L8 (53.95, 20.9123) -> (53.95, 24.0877)
  line L9 (51.2, 19.3246) -> (53.95, 20.9123)
  line L10 (48.759, 20.7339) -> (51.2, 19.3246)
  line L11 (48.759, 9.2661) -> (48.759, 20.7339)
  line L12 (51.2, 10.6754) -> (48.759, 9.2661)
  line L13 (53.95, 9.0877) -> (51.2, 10.6754)
  line L14 (53.95, 5.9123) -> (53.95, 9.0877)
  line L15 (51.2, 4.3246) -> (53.95, 5.9123)
  line L16 (51.2, 3) -> (51.2, 27)
  line L17 (51.2, 9.5) -> (51.2, 22.5)
  line L18 (48.759, 0) -> (48.759, 30)
  line L19 (85.05, -8.5) -> (92.05, -8.5)
  line L20 (85.05, 17) -> (85.05, -8.5)
  line L21 (92.05, -8.5) -> (92.05, 30)
  line L22 (49, -31.75) -> (49, -6.75)
  line L23 (88.55, 37.9254) -> (88.55, -8.5)
  line L24 (48.759, 30) -> (92.05, 30)
  line L25 (55.5, 0) -> (48.759, 0)
  line L26 (55.5, 17) -> (55.5, 0)
  line L27 (85.05, 17) -> (55.5, 17)
  line L28 (46.6404, 0) -> (56.7, 0)
  line L29 (90.8, -1.5) -> (90.8, -4.5)
  line L30 (86.3, -4.5) -> (86.3, -1.5)
  line L31 (88.55, -1.5) -> (88.55, -4.5)
  circle C1 centre (51.2, 22.5) radius 1.67
  circle C2 centre (51.2, 7.5) radius 1.67
  circle C3 centre (51.2, 7.5) radius 1.7
  circle C4 centre (51.2, 22.5) radius 1.7
  arc A1 centre (88.55, -1.5) radius 2.25 clockwise from (86.3, -1.5) to (90.8, -1.5)
  arc A2 centre (88.55, -4.5) radius 2.25 clockwise from (90.8, -4.5) to (86.3, -4.5)
  point P20 (51.2, 22.5)
  point P21 (51.2, 22.5)
  point P24 (48.759, 30)
  point P25 (48.759, 0)
  point P32 (88.55, -8.5)
  point P28 (85.05, 17)
  point P36 (85.05, 17)
  point P38 (51.2, 22.5)
  point P46 (88.55, -1.5)
  point P26 (92.05, -8.5)
  point P27 (85.05, -8.5)
  point P45 (88.55, -4.5)
  point P19 (51.2, 3)
  point P23 (51.2, 7.5)
  vertical L16
  coincident P20 P21
  parallel L16 L17
  collinear L16 L17
  coincident L5 P24
  coincident L2 P25
  perpendicular L19 L20
  perpendicular L19 L21
  midpoint L19 P32
  perpendicular L19 L23
  vertical L21
  perpendicular L5 L24
  collinear L4 L24
  perpendicular L2 L25
  perpendicular L3 L27
  coincident P28 P36
  collinear L3 L26
  concentric C2 C3
  coincident P21 P38
  equal C3 C4
  collinear L25 L28
  tangent L29 A1
  tangent A1 L30
  parallel L29 L30
  tangent L30 A2
  tangent L29 A2
  coincident L23 P46
  parallel L23 L31
  dimension "d535" distance P26 P27 = 7
  dimension "d565" distance L19 P45 = 4
  dimension "d566" distance P19 P45 = 37.35
  dimension "d567" distance P23 P45 = 12
  dimension "d825" distance L24 L27 = 13
  dimension "d833" diameter C4 = 3.4
  dimension "d835" distance L29 L30 = 4.5
  dimension "d836" distance P45 P46 = 3
mirror "Mirror8" mirrorStitchTolerance 0.1 bodies "pcb_holder_adapter2"
extrude "Extrude2" new body sketch "Sketch1" profile of L1 L2 L3 L4 L5 L6 L7 L8 L9 L10 L11 L12 L13 L14 L15 C1 C2 L18 L19 L20 L21 L24 L25 L26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 along normal blind 4
sketch "Sketch2" plane through (0, -2, 0) normal (0, 1, 0) x axis (-1, 0, 0)
  line L1 (-90.8, -1.5) -> (-90.8, -4.5)
  line L2 (-86.3, -4.5) -> (-86.3, -1.5)
  line L3 (-92.05, 30) -> (-48.759, 30)
  line L4 (-92.05, -8.5) -> (-92.05, 30)
  line L5 (-85.05, -8.5) -> (-92.05, -8.5)
  line L6 (-85.05, 17) -> (-85.05, -8.5)
  line L7 (-55.5, 17) -> (-85.05, 17)
  line L8 (-55.5, 0) -> (-55.5, 17)
  line L9 (-48.759, 0) -> (-55.5, 0)
  line L10 (-48.759, 30) -> (-48.759, 0)
  line L11 (-85.05, 5.5) -> (-92.05, 5.5)
  circle C1 centre (-51.2, 22.5) radius 1.67
  circle C2 centre (-51.2, 7.5) radius 1.67
  arc A1 centre (-88.55, -4.5) radius 2.25 clockwise from (-86.3, -4.5) to (-90.8, -4.5)
  arc A2 centre (-88.55, -1.5) radius 2.25 clockwise from (-90.8, -1.5) to (-86.3, -1.5)
  point P18 (-92.05, 5.5)
  point P19 (-85.05, 5.5)
  coincident L4 P18
  coincident L6 P19
  perpendicular L6 L11
  dimension "d842" distance L5 L11 = 14
extrude "Extrude3" cut sketch "Sketch2" profile of C1 C2 A1 L1 A2 L2 L4 L5 L6 L11 against normal blind 1
fillet "Fillet2" radius 2.5
fillet "Fillet5" radius 10
fillet "Fillet6" radius 5
mirror "Mirror1" mirrorStitchTolerance 0.1
component_insert "Component Insert7"
sketch "Sketch1" plane through (72, 0, 0) normal (-1, 0, 0) x axis (0, -1, 0)
  circle C1 centre (3.3676, -9) radius 5.275
  circle C2 centre (3.3676, -9) radius 4.3
  circle C3 centre (3.3676, -9) radius 4
  concentric C2 C3
  dimension "d547" diameter C3 = 8
extrude "Extrude1" new body sketch "Sketch1" profile of C3 against normal blind 9
sketch "Sketch2" plane through (72, 0, 0) normal (-1, 0, 0) x axis (0, -1, 0)
  circle C1 centre (3.3676, -9) radius 4
  circle C2 centre (3.3676, -9) radius 5
  concentric C1 C2
  dimension "d550" diameter C2 = 10
extrude "Extrude2" add sketch "Sketch2" along normal blind 14
sketch "Sketch3" plane through (58, 0, 0) normal (-1, 0, 0) x axis (0, -1, 0)
  line L1 (6.3676, -13) -> (6.3676, -5)
  circle C1 centre (3.3676, -9) radius 5
  point P3 (6.3676, -5)
  point P4 (6.3676, -13)
  coincident C1 P3
  coincident C1 P4
  vertical L1
  dimension "d553" distance P3 P4 = 8
joint "Assemble11" alignAngle 0 alignOffsetX 0 alignOffsetY 0 alignOffsetZ 0.5
extrude "Extrude3" cut sketch "Sketch3" against normal blind 10
work_plane "WorkPlane1" RotateAngle 0
sketch "Sketch4" plane through (68.2689, 1.6324, -9) normal (0, 1, 0) x axis (1, 0, 0)
  line L1 (-5.7189, -4.0992) -> (-9.2689, -2.0496)
  line L2 (-2.1689, -2.0496) -> (-5.7189, -4.0992)
  line L3 (-2.1689, 2.0496) -> (-2.1689, -2.0496)
  line L4 (-5.7189, 4.0992) -> (-2.1689, 2.0496)
  line L5 (-9.2689, 2.0496) -> (-5.7189, 4.0992)
  line L6 (-9.2689, -2.0496) -> (-9.2689, 2.0496)
  line L7 (-10.2689, -5) -> (-10.2689, 5)
  line L8 (-12.188, 0) -> (0, 0)
  circle C1 centre (-5.7189, 0) radius 2.25
  point P2 (-5.7189, 0)
  point P9 (-5.7189, 0)
  point P1 (0, 0)
  point P12 (0, 0)
  coincident P2 P9
  vertical L6
  coincident P1 P12
  perpendicular L3 L8
  coincident P9 L8
  dimension "d557" diameter C1 = 4.5
  dimension "d558" distance L3 L6 = 7.1
  dimension "d559" distance L6 L7 = 1
extrude "Extrude4" cut sketch "Sketch4" profile of C1 no distance stored
extrude "Extrude5" cut sketch "Sketch4" profile of C1 L1 L2 L3 L4 L5 L6 against normal blind 2
work_plane "WorkPlane2" RotateAngle 0
work_plane "WorkPlane3" RotateAngle -90
work_plane "WorkPlane4"
sketch "Sketch5" plane through (0, -3.3676, 0) normal (0, 1, 0) x axis (1, 0, 0)
  line L1 (80.1, 5) -> (79.1, 5)
  line L2 (80.1, 5.5) -> (80.1, 5)
  line L3 (79.1, 5.5) -> (80.1, 5.5)
  line L4 (79.1, 5) -> (79.1, 5.5)
  line L5 (76.9096, 9) -> (85.0904, 9)
  line L6 (81, 13) -> (81, 5)
  line L7 (72, 5) -> (72, 13)
  line L8 (76.1, 5) -> (81, 5)
  point P8 (81, 5)
  point P12 (81, 5)
  point P2 (79.1, 5)
  point P3 (80.1, 5)
  horizontal L1
  vertical L2
  horizontal L3
  vertical L4
  horizontal L5
  midpoint L5 L6
  coincident P8 P12
  perpendicular L6 L8
  collinear L1 L8
  dimension "d568" distance P2 P3 = 1
  dimension "d569" = 7
  dimension "d570" distance L4 L7 = 7.1
revolve "Revolve1" sketch "Sketch5" AlongAngle 360
chamfer "Chamfer1" distance 0.5
chamfer "Chamfer2" distance 1
joint "Assemble13" alignAngle 90 alignOffsetX 0 alignOffsetY 0 alignOffsetZ 0
joint "Assemble15" alignAngle 180 alignOffsetX 0 alignOffsetY 0 alignOffsetZ 0
sketch "Sketch6" plane through (81, 0, 0.0247) normal (1, 0, 0) x axis (0, 1, 0)
  line L1 (1.2464, -14.2888) -> (-0.3676, -10.8275)
  line L2 (-7.9816, -14.2888) -> (-6.3676, -10.8275)
  line L3 (-9.2764, -7.9828) -> (-6.8144, -8.4169)
  line L4 (-4.9205, -3.2291) -> (-4.2735, -5.644)
  line L5 (-1.8147, -3.2291) -> (-2.4617, -5.644)
  line L6 (2.5412, -7.9828) -> (0.0792, -8.4169)
  line L7 (-3.3676, 1) -> (-3.3676, -16.8891)
  line L8 (-11.5638, -7.5795) -> (-3.3676, -9.0247)
  line L9 (-5.5541, -0.8647) -> (-3.3676, -9.0247)
  circle C1 centre (-3.3676, -9.0247) radius 4
  circle C2 centre (-3.3676, -9.0247) radius 3.5
  circle C3 centre (-3.3676, -9.0247) radius 7
  circle C4 centre (-3.3676, -9.0247) radius 6
  arc A1 centre (-3.3676, -9.0247) radius 7 clockwise from (-7.9816, -14.2888) to (1.2464, -14.2888)
  arc A2 centre (-3.3676, -9.0247) radius 3.5 clockwise from (-6.3676, -10.8275) to (-6.8144, -8.4169)
  arc A3 centre (-3.3676, -9.0247) radius 6 clockwise from (-9.2764, -7.9828) to (-4.9205, -3.2291)
  arc A4 centre (-3.3676, -9.0247) radius 3.5 clockwise from (-4.2735, -5.644) to (-2.4617, -5.644)
  arc A5 centre (-3.3676, -9.0247) radius 6 clockwise from (-1.8147, -3.2291) to (2.5412, -7.9828)
  arc A6 centre (-3.3676, -9.0247) radius 3.5 clockwise from (0.0792, -8.4169) to (-0.3676, -10.8275)
  point P5 (-0.3676, -10.8275)
  point P6 (1.2464, -14.2888)
  point P7 (-6.3676, -10.8275)
  point P8 (-7.9816, -14.2888)
  point P10 (-6.8144, -8.4169)
  point P11 (-9.2764, -7.9828)
  point P12 (-4.2735, -5.644)
  point P13 (-4.9205, -3.2291)
  point P14 (-2.4617, -5.644)
  point P15 (-1.8147, -3.2291)
  point P16 (0.0792, -8.4169)
  point P17 (2.5412, -7.9828)
  point P3 (-3.3676, -9.0247)
  point P9 (-3.3676, -9.0247)
  point P20 (-3.3676, -9.0247)
  point P22 (-3.3676, -9.0247)
  point P24 (-3.3676, -9.0247)
  point P4 (-3.3676, -9.0247)
  point P25 (-3.3676, -9.0247)
  point P27 (-3.3676, -9.0247)
  point P29 (-3.3676, -9.0247)
  point P26 (-3.3676, -9.0247)
  point P28 (-3.3676, -9.0247)
  concentric C1 C2
  concentric C2 C3
  coincident C2 P5
  coincident C3 P6
  coincident C2 P7
  coincident C3 P8
  concentric C3 C4
  coincident C2 P10
  coincident C4 P11
  coincident C2 P12
  coincident C4 P13
  coincident C2 P14
  coincident C4 P15
  coincident C2 P16
  coincident C4 P17
  vertical L7
  coincident P3 L7
  symmetric L4 L5 L7
  symmetric L3 L6 L7
  symmetric L1 L2 L7
  coincident P9 P20
  collinear L3 L8
  coincident P3 P22
  collinear L4 L9
  coincident P3 P24
  coincident P4 P25
  coincident P4 P27
  coincident P4 P29
  coincident P26 P28
  dimension "d597" diameter C2 = 7
  dimension "d598" diameter C3 = 14
  dimension "d599" diameter C4 = 12
  dimension "d600" angle L4 L5 = 30
  dimension "d601" angle L3 L6 = 160
  dimension "d602" angle L1 L2 = 50
  dimension "d603" distance P5 P7 = 6
extrude "Extrude6" new body sketch "Sketch6" profile of C1 L1 L2 L3 L4 L5 L6 A1 A2 A3 A4 A5 A6 along normal blind 0.9
fillet "Fillet1" radius 1.25
fillet "Fillet2" radius 0.8
work_plane "WorkPlane25" RotateAngle 0
sketch "Sketch32" plane through (0, 47, -25.1651) normal (0, 1, 0) x axis (1, 0, 0)
  line L1 (-12.5, 9.8349) -> (12.5, 9.8349)
  line L2 (-12.5, -2.1651) -> (-12.5, 9.8349)
  line L3 (12.5, -2.1651) -> (-12.5, -2.1651)
  line L4 (12.5, 9.8349) -> (12.5, -2.1651)
  line L5 (0, -47.6651) -> (0, -26.9151)
  line L6 (47, 14.8349) -> (-47, 14.8349)
  point P2 (12.5, 9.8349)
  point P5 (12.5, -2.1651)
  point P4 (-12.5, -2.1651)
  horizontal L1
  vertical L2
  horizontal L3
  vertical L4
  symmetric L2 L4 L5
  dimension "d614" distance P2 P5 = 12
  dimension "d615" distance P4 P5 = 25
  dimension "d916" distance L1 L6 = 5
extrude "Extrude21" new body sketch "Sketch32" profile of L1 L2 L3 L4 to an object second side blind -1 bodies "battery_holder"
sketch "Sketch33" plane through (0, 48, 0) normal (0, 1, 0) x axis (-1, 0, 0)
  line L1 (12.5, -23) -> (12.5, -35)
  line L2 (-12.5, -23) -> (12.5, -23)
  line L3 (-12.5, -35) -> (-12.5, -23)
  line L4 (12.5, -35) -> (-12.5, -35)
  line L5 (12.5, -35) -> (-12.5, -35)
  line L6 (12.5, -33) -> (12.5, -35)
  line L7 (-11, -33) -> (11, -33)
  line L8 (-12.5, -35) -> (-12.5, -33)
  line L9 (-11, -31.5) -> (-11, -33)
  line L10 (-12.5, -31.5) -> (-11, -31.5)
  line L11 (-12.5, -33) -> (-12.5, -31.5)
  line L12 (11, -31.5) -> (11, -33)
  line L13 (12.5, -31.5) -> (11, -31.5)
  line L14 (12.5, -33) -> (12.5, -31.5)
  point P8 (12.5, -33)
  point P5 (-12.5, -35)
  point P6 (-12.5, -35)
  point P11 (-11, -31.5)
  point P12 (-12.5, -31.5)
  point P10 (-11, -33)
  horizontal L5
  vertical L6
  horizontal L7
  vertical L8
  coincident L1 P8
  coincident P5 P6
  vertical L9
  horizontal L10
  vertical L11
  vertical L12
  horizontal L13
  vertical L14
  equal L10 L13
  equal L9 L12
  dimension "d623" distance L5 L7 = 2
  dimension "d624" distance P11 P12 = 1.5
  dimension "d625" distance P10 P11 = 1.5
extrude "Extrude22" add sketch "Sketch33" profile of L1 L3 L4 L5 L6 L7 L8 along normal blind 20
chamfer "Chamfer21" distance 1.5 Rotate Angle 45
mirror "Mirror13" mirrorStitchTolerance 0.1 bodies "battery_holder (1)"
sketch "Sketch35" plane through (49, 0, 0) normal (1, 0, 0) x axis (0, 1, 0)
  line L1 (17.5, -36.75) -> (-17.5, -36.75)
  line L2 (17.5, -1.75) -> (17.5, -36.75)
  line L3 (-17.5, -1.75) -> (17.5, -1.75)
  line L4 (-17.5, -36.75) -> (-17.5, -1.75)
  line L5 (0, -31.0416) -> (0, -8.0416)
  line L6 (23.4689, -19.25) -> (-22.0561, -19.25)
  line L7 (-15.25, -34.5) -> (-15.25, -4)
  line L8 (12.5, -6.75) -> (12.5, -31.75)
  line L9 (-12.5, -6.75) -> (12.5, -6.75)
  line L10 (-12.5, -31.75) -> (-12.5, -6.75)
  line L11 (12.5, -31.75) -> (-12.5, -31.75)
  line L12 (12.5, -6.75) -> (-12.5, -6.75)
  line L13 (12.5, -31.75) -> (12.5, -6.75)
  line L14 (-12.5, -31.75) -> (12.5, -31.75)
  line L15 (-12.5, -6.75) -> (-12.5, -31.75)
  line L16 (0, -19.25) -> (-13.4822, -5.7678)
  line L17 (-13.4822, -32.7322) -> (13.4822, -5.7678)
  line L18 (17.0178, -5.7678) -> (-13.4822, -36.2678)
  line L19 (-3.5355, -19.25) -> (-17.0178, -5.7678)
  line L20 (0, -15.7145) -> (-13.4822, -2.2322)
  line L21 (0, -15.7145) -> (13.4822, -2.2322)
  line L22 (-17.0178, -32.7322) -> (-3.5355, -19.25)
  circle C1 centre (-15.25, -4) radius 2.5
  circle C2 centre (15.25, -4) radius 2.5
  circle C3 centre (-15.25, -34.5) radius 2.5
  circle C4 centre (-15.25, -4) radius 1.4
  circle C5 centre (15.25, -4) radius 1.4
  circle C6 centre (-15.25, -34.5) radius 1.4
  point P6 (-15.25, -4)
  point P7 (15.25, -4)
  point P13 (-15.25, -4)
  point P8 (-15.25, -34.5)
  point P14 (-15.25, -34.5)
  point P18 (12.5, -31.75)
  point P24 (12.5, -31.75)
  point P20 (-12.5, -6.75)
  point P22 (-12.5, -6.75)
  point P26 (-13.4822, -5.7678)
  point P27 (0, -19.25)
  point P28 (13.4822, -5.7678)
  point P29 (-13.4822, -32.7322)
  point P23 (12.5, -6.75)
  point P30 (13.4822, -2.2322)
  point P31 (-17.0178, -32.7322)
  point P32 (-13.4822, -36.2678)
  point P33 (17.0178, -5.7678)
  point P34 (-17.0178, -5.7678)
  point P35 (-3.5355, -19.25)
  point P36 (-13.4822, -2.2322)
  equal C1 C3
  equal C1 C2
  perpendicular L3 L5
  symmetric L2 L4 L5
  perpendicular L2 L6
  symmetric L1 L3 L6
  symmetric P6 P7 L5
  coincident P6 P13
  coincident P8 P14
  vertical L7
  symmetric P6 P8 L6
  concentric C1 C4
  concentric C2 C5
  concentric C3 C6
  equal C4 C6
  equal C4 C5
  horizontal L12
  vertical L13
  horizontal L14
  vertical L15
  coincident P18 P24
  coincident P20 P22
  coincident C1 P26
  coincident L6 P27
  coincident L5 P27
  coincident C2 P28
  coincident C3 P29
  perpendicular L16 L17
  coincident P23 L17
  coincident P22 L16
  coincident C2 P30
  coincident C3 P31
  coincident C3 P32
  coincident C2 P33
  parallel L18 L21
  coincident C1 P34
  coincident P35 L21
  perpendicular L19 L21
  coincident C1 P36
  perpendicular L20 L21
  symmetric L16 L19 L20
  collinear L21 L22
  tangent C1 L20
  tangent C2 L21
  dimension "d631" diameter C1 = 5
  dimension "d632" distance P6 P7 = 30.5
  dimension "d633" distance P6 P8 = 30.5
  dimension "d634" diameter C4 = 2.8
extrude "Extrude27" new body sketch "Sketch35" profile of C1 C2 C3 C4 C5 C6 L8 L9 L10 L11 L12 L13 L14 L15 L22 L18 L19 L20 along normal blind 1 bodies "pcb_holder_30.5x30.5"
sketch "Sketch38" plane through (50, 0, 0) normal (1, 0, 0) x axis (0, 1, 0)
  line L1 (-12.5, -10.2855) -> (-17.0178, -5.7678)
  line L2 (-12.5, -28.2145) -> (-12.5, -10.2855)
  line L3 (-17.0178, -32.7322) -> (-12.5, -28.2145)
  line L4 (-8.9645, -31.75) -> (-13.4822, -36.2678)
  line L5 (12.5, -31.75) -> (-8.9645, -31.75)
  line L6 (12.5, -10.2855) -> (12.5, -31.75)
  line L7 (17.0178, -5.7678) -> (12.5, -10.2855)
  line L8 (8.9645, -6.75) -> (13.4822, -2.2322)
  line L9 (-8.9645, -6.75) -> (8.9645, -6.75)
  line L10 (-13.4822, -2.2322) -> (-8.9645, -6.75)
  arc A1 centre (-15.25, -4) radius 2.5 clockwise from (-17.0178, -5.7678) to (-13.4822, -2.2322)
  arc A2 centre (-15.25, -34.5) radius 2.5 clockwise from (-13.4822, -36.2678) to (-17.0178, -32.7322)
  arc A3 centre (15.25, -4) radius 2.5 clockwise from (13.4822, -2.2322) to (17.0178, -5.7678)
  circle C1 centre (15.25, -4) radius 1.4
  circle C2 centre (-15.25, -4) radius 1.4
  circle C3 centre (-15.25, -34.5) radius 1.4
  circle C4 centre (-15.25, -34.5) radius 2.5
  circle C5 centre (-15.25, -4) radius 2.5
  circle C6 centre (15.25, -4) radius 2.5
extrude "Extrude28" add sketch "Sketch38" profile of A1 A2 A3 C1 C2 C3 C4 C5 C6 along normal blind 6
